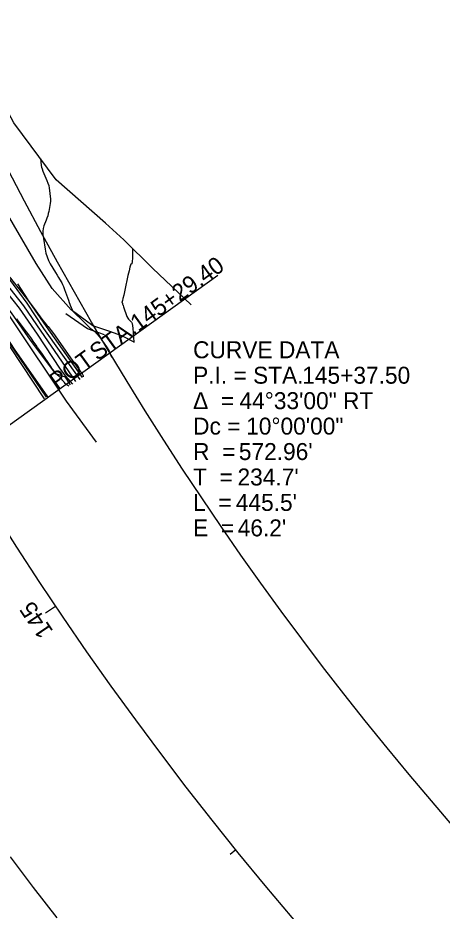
# Model space of a CAD drawing. Extents: x 2030588 to 2035216, y 462285 to 465007.
# Drawn here: x 2031348.7 to 2031418.7, y 463951.1 to 464098.6 of the extents above; entities that cross this region are included whole.
import ezdxf

# ---------------------------------------------------------------- set-up
doc = ezdxf.new("R2010")
doc.units = 0
for name, color, linetype in [('DR_X_Ditch', 7, 'Continuous'), ('DT_X_Contour_Minor', 7, 'Continuous'), ('GE_X_Alignment_100_Cardinal_Points', 7, 'Continuous'), ('PV_X_EOP', 7, 'Continuous'), ('PV_X_Shoulder_Aggregate', 7, 'Continuous'), ('RW_X_CL', 7, 'Continuous'), ('RW_X_CL_100_Curve_Data', 7, 'Continuous'), ('RW_X_CL_100_Stations', 7, 'Continuous'), ('RW_X_Esmt_SH', 7, 'Continuous'), ('SV_X_Break_Lines', 7, 'Continuous'), ('SV_X_Toe_of_Slope', 7, 'Continuous'), ('SV_X_Top_of_Bank', 7, 'Continuous'), ('UT_X_Telecom', 7, 'Continuous')]:
    doc.layers.add(name, color=color, linetype=linetype)

msp = doc.modelspace()

# ---------------------------------------------------------------- linework, layer by layer
at = {"layer": 'DR_X_Ditch'}
msp.add_lwpolyline([(2031358.31, 464038.57), (2031352.6, 464046.87), (2031349.71, 464051.04), (2031346.63, 464054.97), (2031344.08, 464058.42), (2031340.98, 464063.62), (2031338.93, 464066.94), (2031337.46, 464068.44), (2031334.32, 464073.31), (2031331.96, 464077.26), (2031329.91, 464080.56), (2031327.01, 464085.85), (2031325.25, 464089.45), (2031320.92, 464098.05), (2031317.25, 464106.19)], dxfattribs=at)
at = {"layer": 'DT_X_Contour_Minor'}
for points in [[(2031352.45, 464075.37), (2031352.59, 464074.24), (2031352.64, 464073.97), (2031352.73, 464073.66), (2031352.86, 464073.3), (2031353.03, 464072.89), (2031353.53, 464071.74), (2031353.7, 464071.31), (2031353.83, 464070.9), (2031353.93, 464070.5), (2031353.98, 464070.11), (2031354.09, 464069.1), (2031354.11, 464068.72), (2031354.11, 464068.35), (2031354.08, 464067.97), (2031354.02, 464067.61), (2031353.83, 464066.63), (2031353.76, 464066.27), (2031353.66, 464065.9), (2031353.54, 464065.54), (2031353.41, 464065.19), (2031353.03, 464064.24), (2031352.92, 464063.84), (2031352.87, 464063.37), (2031352.88, 464062.82), (2031352.95, 464062.19), (2031353.23, 464060.4), (2031353.36, 464059.75), (2031353.55, 464059.13), (2031353.79, 464058.55), (2031354.08, 464058), (2031354.93, 464056.58), (2031355.22, 464056.11), (2031355.44, 464055.73), (2031355.61, 464055.46), (2031355.72, 464055.3), (2031355.91, 464054.99), (2031356, 464054.83), (2031356.12, 464054.57), (2031356.26, 464054.22), (2031356.42, 464053.77), (2031356.91, 464052.43), (2031357.07, 464051.97), (2031357.21, 464051.61), (2031357.31, 464051.33), (2031357.39, 464051.15), (2031357.54, 464050.78), (2031357.6, 464050.65), (2031357.64, 464050.55), (2031357.66, 464050.48), (2031357.68, 464050.43), (2031357.72, 464050.26), (2031359.73, 464048.29), (2031360.12, 464047.91), (2031360.44, 464047.61), (2031360.68, 464047.39), (2031360.84, 464047.26), (2031361.44, 464046.82), (2031362.14, 464045.98), (2031362.3, 464045.78), (2031362.47, 464045.55), (2031362.67, 464045.28), (2031362.88, 464044.98), (2031363.46, 464044.12), (2031363.66, 464043.82), (2031363.81, 464043.57), (2031363.92, 464043.36), (2031363.99, 464043.2), (2031364.2, 464042.56)], [(2031367.67, 464060.5), (2031367.62, 464058.8), (2031367.61, 464058.47), (2031367.58, 464058.23), (2031367.55, 464058.08), (2031367.51, 464058.01), (2031367.39, 464057.93), (2031367.32, 464057.79), (2031367.22, 464057.43), (2031367.07, 464056.85), (2031366.89, 464056.06), (2031366.36, 464053.64), (2031366.19, 464052.84), (2031366.06, 464052.26), (2031365.98, 464051.91), (2031365.94, 464051.78), (2031365.92, 464051.72), (2031365.91, 464051.7), (2031365.91, 464051.68), (2031365.91, 464051.65), (2031365.92, 464051.63), (2031365.95, 464051.56), (2031365.96, 464051.54), (2031365.97, 464051.51), (2031365.98, 464051.48), (2031365.98, 464051.44), (2031366.01, 464051.34), (2031366.03, 464051.26), (2031366.08, 464051.1), (2031366.16, 464050.87), (2031366.27, 464050.55), (2031366.6, 464049.6), (2031366.73, 464049.28), (2031366.85, 464049.03), (2031366.96, 464048.84), (2031367.08, 464048.72), (2031367.38, 464048.49), (2031367.48, 464048.36), (2031367.57, 464048.12), (2031367.64, 464047.78), (2031367.69, 464047.35), (2031367.89, 464045.07), (2031367.91, 464045.03)], [(2031348.67, 464054.7), (2031350.39, 464052.04), (2031350.46, 464051.94), (2031350.48, 464051.91), (2031350.5, 464051.89), (2031350.51, 464051.87), (2031350.53, 464051.85), (2031350.57, 464051.8), (2031350.59, 464051.76), (2031350.64, 464051.7), (2031350.71, 464051.6), (2031350.8, 464051.48), (2031351.26, 464050.82), (2031352.87, 464048.66), (2031353.18, 464048.26), (2031353.41, 464047.96), (2031353.57, 464047.77), (2031353.64, 464047.69), (2031353.75, 464047.62), (2031353.89, 464047.45), (2031354.23, 464047), (2031354.76, 464046.26), (2031355.49, 464045.23), (2031357.69, 464042.11), (2031358.42, 464041.09), (2031358.94, 464040.34), (2031359.27, 464039.88), (2031359.39, 464039.71), (2031359.44, 464039.63), (2031359.46, 464039.6), (2031359.48, 464039.57), (2031359.49, 464039.53), (2031359.5, 464039.5), (2031359.53, 464039.35)], [(2031357.13, 464037.78), (2031356.8, 464038.04), (2031356.73, 464038.09), (2031356.67, 464038.15), (2031356.61, 464038.2), (2031356.56, 464038.25), (2031356.44, 464038.39), (2031356.39, 464038.45), (2031356.32, 464038.52), (2031356.24, 464038.61), (2031356.15, 464038.72), (2031355.9, 464039.04), (2031355.8, 464039.15), (2031355.7, 464039.26), (2031355.6, 464039.36), (2031355.5, 464039.45), (2031355.01, 464039.84), (2031355, 464039.85), (2031355, 464039.85), (2031355, 464039.85), (2031355, 464039.85), (2031355, 464039.85), (2031355, 464039.85), (2031354.94, 464039.94), (2031354.76, 464040.2), (2031354.46, 464040.62), (2031354.05, 464041.23), (2031352.78, 464043.06), (2031352.35, 464043.68), (2031352.01, 464044.18), (2031351.76, 464044.54), (2031351.6, 464044.78), (2031351.28, 464045.24), (2031351.12, 464045.47), (2031350.88, 464045.8), (2031350.56, 464046.24), (2031350.16, 464046.79), (2031348.98, 464048.38), (2031348.59, 464048.92)]]:
    msp.add_lwpolyline(points, dxfattribs=at)
at = {"layer": 'GE_X_Alignment_100_Cardinal_Points'}
msp.add_line((2031345.19, 464029.83), (2031381.7, 464056.12), dxfattribs=at)
at = {"layer": 'PV_X_EOP'}
msp.add_lwpolyline([(2031353.16, 464035.71), (2031341.87, 464052.68), (2031332.72, 464067.74), (2031330.52, 464071.93), (2031322.02, 464088.2), (2031314.11, 464105.1), (2031307.35, 464122.15), (2031301.27, 464138.47), (2031296.14, 464154.31), (2031290.95, 464171.99), (2031286.32, 464189.89), (2031281.44, 464210.56), (2031280.32, 464215.54), (2031275.67, 464237.43), (2031271.64, 464258.65), (2031268.07, 464277.87), (2031264.48, 464299.11), (2031261, 464318.44), (2031259.92, 464324.37)], dxfattribs=at)
at = {"layer": 'PV_X_Shoulder_Aggregate'}
msp.add_lwpolyline([(2031353.45, 464035.96), (2031344.86, 464048.59), (2031343.78, 464050.85), (2031343.2, 464053.48), (2031340.63, 464057.47), (2031339.88, 464057.53), (2031337.67, 464061.76), (2031335.45, 464064.49), (2031332.72, 464067.74), (2031330.52, 464071.93), (2031330.53, 464073.67), (2031322.8, 464088.62), (2031315.02, 464105.5)], dxfattribs=at)
at = {"layer": 'RW_X_CL'}
msp.add_ellipse((2031830.08, 464321.52), major_axis=(-382.72, 426.32), ratio=0.999987, start_param=0.998751, end_param=1.776295, dxfattribs=at)
at = {"layer": 'RW_X_CL_100_Stations'}
for p, q in [((2031354.96, 464001.42), (2031353.3, 464000.3)), ((2031384.66, 463961.23), (2031383.73, 463960.47))]:
    msp.add_line(p, q, dxfattribs=at)
at = {"layer": 'RW_X_Esmt_SH'}
for points in [[(2031420.64, 463965.02), (2031416.92, 463969.34), (2031413.24, 463973.7), (2031409.61, 463978.1), (2031406.02, 463982.53), (2031402.48, 463987.01), (2031398.99, 463991.52), (2031395.55, 463996.07), (2031392.15, 464000.65), (2031388.8, 464005.27), (2031385.51, 464009.92), (2031382.26, 464014.61), (2031379.06, 464019.34), (2031375.91, 464024.09), (2031372.81, 464028.88), (2031369.76, 464033.7), (2031366.76, 464038.55), (2031363.81, 464043.44), (2031360.91, 464048.35), (2031358.07, 464053.3), (2031355.28, 464058.27), (2031352.54, 464063.27), (2031349.85, 464068.31), (2031347.22, 464073.37)], [(2031355.23, 463950.04), (2031351.35, 463955.05), (2031347.53, 463960.1)]]:
    msp.add_lwpolyline(points, dxfattribs=at)
at = {"layer": 'SV_X_Break_Lines'}
for points in [[(2031353.71, 464036.03), (2031348.18, 464043.89), (2031344.73, 464049.19)], [(2031363.04, 464046.25), (2031360.24, 464047.24), (2031356.64, 464049.76)]]:
    msp.add_lwpolyline(points, dxfattribs=at)
at = {"layer": 'SV_X_Toe_of_Slope'}
for points in [[(2031377.32, 464051.22), (2031370.93, 464057.29), (2031366.21, 464061.95), (2031363.2, 464064.72), (2031355.06, 464071.84), (2031348.1, 464081.25), (2031345.52, 464086), (2031340.81, 464096.95), (2031339.1, 464101.93), (2031337.64, 464105.74), (2031336.42, 464112.21), (2031336.17, 464116.67), (2031335.18, 464119.71), (2031334.24, 464127.5), (2031333.88, 464132.12), (2031332.75, 464135.26)], [(2031357.82, 464038.13), (2031356.64, 464039.45), (2031355.8, 464040.62), (2031351.96, 464046.37), (2031349.02, 464050.65), (2031345.87, 464054.63), (2031343.43, 464058.02), (2031340.43, 464063.29), (2031338.41, 464066.63), (2031336.3, 464067.5), (2031335.53, 464069.3), (2031333.52, 464072.96), (2031332.14, 464075.56), (2031331.16, 464076.87), (2031329.12, 464080.18), (2031326.36, 464085.5), (2031324.64, 464089.33), (2031319.94, 464097.81), (2031316.49, 464105.9)], [(2031318.18, 464106.58), (2031321.74, 464098.44), (2031325.87, 464089.83), (2031327.57, 464086.14), (2031330.98, 464080.94), (2031333.03, 464077.81), (2031335.14, 464073.96), (2031341.46, 464064), (2031344.55, 464058.78), (2031347.37, 464055.42), (2031350.24, 464051.52), (2031352.99, 464047.3), (2031358.95, 464038.9)]]:
    msp.add_lwpolyline(points, dxfattribs=at)
at = {"layer": 'SV_X_Top_of_Bank'}
for points in [[(2031367.93, 464045.05), (2031365.91, 464046.11), (2031363.9, 464046.82), (2031361.13, 464047.76), (2031357.51, 464050.41), (2031354.38, 464053.9), (2031351.75, 464058.03), (2031346.67, 464066.86), (2031339.34, 464075.88), (2031337.02, 464080.22), (2031334.82, 464082.7), (2031332.41, 464088.43), (2031330.92, 464092.36), (2031327.35, 464100.77)], [(2031357.45, 464038), (2031356.62, 464039.28), (2031354.99, 464039.85), (2031350.82, 464045.4), (2031347.7, 464049.92), (2031344.62, 464053.83), (2031342.53, 464057.54), (2031339.53, 464062.82), (2031337.56, 464066.28), (2031335.47, 464066.94), (2031332.93, 464072.63), (2031331.46, 464075.05), (2031330.02, 464076.29), (2031328.41, 464080.03), (2031325.43, 464085.25), (2031324.01, 464089.07), (2031319.57, 464097.72)], [(2031359.38, 464039.25), (2031353.44, 464047.67), (2031350.61, 464051.76), (2031347.56, 464055.6), (2031344.55, 464058.78)]]:
    msp.add_lwpolyline(points, dxfattribs=at)
at = {"layer": 'UT_X_Telecom'}
msp.add_lwpolyline([(2031361.71, 464028.54), (2031356.79, 464035.33), (2031347.68, 464048.93), (2031339.94, 464060.4), (2031329.73, 464073.81), (2031321.67, 464087.15), (2031313.33, 464106.65), (2031305.91, 464124.39), (2031298.72, 464143.46), (2031292.6, 464165.64), (2031287.04, 464187.23), (2031282.35, 464208.08), (2031277.6, 464228.83), (2031275.08, 464242.09), (2031273.13, 464253.29), (2031272.71, 464257.73), (2031274.4, 464259.6), (2031278.69, 464259.87), (2031283.76, 464259.77), (2031285.5, 464261.09)], dxfattribs=at)

# ---------------------------------------------------------------- texts
at = {"layer": 'GE_X_Alignment_100_Cardinal_Points'}
for s, p in [('145+29.40', (2031368.58, 464046.72)), (' STA. ', (2031361.01, 464041.27)), ('POT', (2031355.23, 464037.11))]:
    msp.add_text(s, height=2.8, rotation=35.7565, dxfattribs=at).set_placement(p)
at = {"layer": 'RW_X_CL_100_Curve_Data'}
for s, height, p in [('CURVE DATA', 2.8, (2031377.64, 464042.4)), ('P.I. = STA. ', 2.7997, (2031377.64, 464038.2)), ('145+37.50', 2.8, (2031395.63, 464038.2)), ('Δ  = ', 2.8, (2031377.64, 464034)), ('44°33\'00" RT', 2.7997, (2031385.29, 464034)), ('Dc = ', 2.8, (2031377.64, 464029.8)), ('10°00\'00"', 2.8, (2031386.39, 464029.8)), ('R  = ', 2.8, (2031377.64, 464025.6)), ("572.96'", 2.8, (2031385.18, 464025.6)), ('T  = ', 2.8, (2031377.64, 464021.4)), ("234.7'", 2.8, (2031384.96, 464021.4)), ('L  = ', 2.8, (2031377.64, 464017.2)), ("445.5'", 2.8, (2031384.68, 464017.2)), ('E  = ', 2.8, (2031377.64, 464013)), ("46.2'", 2.8, (2031384.99, 464013))]:
    msp.add_text(s, height=height, rotation=359.9993, dxfattribs=at).set_placement(p)
at = {"layer": 'RW_X_CL_100_Stations'}
msp.add_text('145', height=2.8, rotation=123.9693, dxfattribs=at).set_placement((2031354.67, 463997.36))

doc.saveas('drawing.dxf')
